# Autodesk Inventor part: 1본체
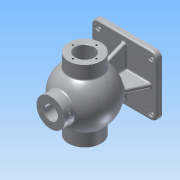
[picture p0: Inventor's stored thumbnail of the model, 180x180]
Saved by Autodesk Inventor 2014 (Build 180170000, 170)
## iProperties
Created: 2017-01
Part Number: 1본체
Material: Aluminum 6061
Document SubType Name: Modeling
Designer: ksu
Density: 2.71 g/cm^3
Appearance: Aluminum - Flat
Mass: 1507.18 g
Surface Area: 1153.3 cm^2
Volume: 556.155 cm^3
Author: ksu
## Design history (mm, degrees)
sketch "Sketch1"
  geometry: L1 (-50.5, -57.5)-(50.5, -57.5); L2 (62.5, -45.5)-(62.5, 45.5); L3 (50.5, 57.5)-(-50.5, 57.5); L4 (-62.5, 45.5)-(-62.5, -45.5); L5 (-62.5, -57.5)-(62.5, 57.5); L6 (62.5, -57.5)-(-62.5, 57.5); A1 r 12 centre (-50.5, 45.5) between (-50.5, 57.5) and (-62.5, 45.5); A2 r 12 centre (-50.5, -45.5) between (-62.5, -45.5) and (-50.5, -57.5); A3 r 12 centre (50.5, -45.5) between (50.5, -57.5) and (62.5, -45.5); A4 r 12 centre (50.5, 45.5) between (62.5, 45.5) and (50.5, 57.5); 1 further point
  constraints: 12 end point, 8 point on circle, 8 point on line, 8 tangent, 4 centre point, 3 equal radius, 2 midpoint, 2 parallel, 1 horizontal, 1 perpendicular
  dimensions: "d0" = 125 distance of L6.end L5.end; "d1" = 115 distance of L5.end L6.start; "d2" = 12 radius of A1
extrude "Extrusion1" new body sketch "Sketch1" distance "d3" = 10; taper "d4" = 0 deg
sketch "Sketch2"
  geometry: L1 (0, 85)-(-53, 85); L2 (-53, 85)-(53, 85); A1 r 53 centre (0, 85) between (53, 85) and (-53, 85); 1 further point
  constraints: 4 end point, 2 point on circle, 1 centre point, 1 collinear, 1 horizontal
  dimensions: "d5" = 106 diameter of A1; "d6" = 85 distance of point (0, 0) L1.start
revolve "Revolution1" sketch "Sketch2" stored, may be unused: angle "d7" = 90 deg
sketch "Sketch3"
  geometry: C1 r 53 at (0, 85) reference; C2 r 31 at (0, 85); 1 further point
  constraints: 1 centre point, 1 coincident
  dimensions: "d8" = 62 diameter of C2
extrude "Extrusion2" join sketch "Sketch3" stored distance "d9" = 136; taper "d10" = 0 deg
workplane "Work Plane1"
sketch "Sketch4"
  geometry: C1 r 27 at (0, 0); 1 further point
  constraints: 1 centre point, 1 coincident
  dimensions: "d12" = 54 diameter of C1
extrude "Extrusion3" join sketch "Sketch4" distance "d13" = 30; taper "d14" = 0 deg
sketch "Sketch5"
  geometry: C1 r 31 at (0, 0) reference; C2 r 17.5 at (0, 0); 1 further point
  constraints: 1 centre point, 1 coincident
  dimensions: "d15" = 35 diameter of C2
extrude "Extrusion4" cut sketch "Sketch5" distance "d16" = 136; taper "d17" = 0 deg
sketch "Sketch6"
  geometry: C1 r 27 at (0, 0) reference; C2 r 13 at (0, 0)
  constraints: 1 centre point, 1 coincident
  dimensions: "d18" = 26 diameter of C2
sketch "Sketch7"
  geometry: L1 (-43, 85)-(43, 85); A1 r 53 centre (0, 85) between (42.988, 116) and (42.988, 54) reference; A2 r 43 centre (0, 85) between (43, 85) and (-43, 85); 1 further point
  constraints: 2 end point, 2 point on circle, 1 centre point, 1 coincident, 1 horizontal
  dimensions: "d19" = 86 diameter of A2
revolve "Revolution2" sketch "Sketch7" stored, may be unused: angle "d20" = 90 deg
sketch "Sketch8"
  geometry: 1 further point
extrude "Extrusion5" cut sketch "Sketch6" distance "d21" = 30; taper "d22" = 0 deg
sketch "Sketch9"
  geometry: 1 further point
sketch "Sketch10"
  geometry: L1 (45.5, 10)-(-45.5, 10) reference; L2 (57.5, 10)-(47.5, 10); L3 (47.5, 10)-(32.011, 48.336); L4 (0, 0)-(0, 23.921); L5 (57.5, 0)-(57.5, 10) reference; L6 (-47.5, 10)-(-32.011, 48.336); L7 (-57.5, 10)-(-45.5, 10); L8 (-47.5, 10)-(47.5, 10); A1 r 53 centre (0, 85) between (42.988, 116) and (42.988, 54) reference; A2 r 48.672 centre (0, 85) between (32.011, 48.336) and (-32.011, 48.336); 2 further points
  constraints: 12 end point, 3 point on circle, 3 point on line, 2 symmetric about line, 1 centre point, 1 coincident, 1 collinear, 1 perpendicular
  dimensions: "d23" = 10 distance of L2.start L2.end; "d24" = 22 deg angle of L5 L3
extrude "Extrusion6" join sketch "Sketch10" stored distance "d25" = 8; taper "d26" = 0 deg
sketch "Sketch12"
  geometry: L1 (50.5, 10)-(-50.5, 10) reference; L2 (62.5, 0)-(62.5, 10) reference; L3 (62.5, 10)-(52.5, 10); L4 (52.5, 10)-(35.258, 52.676); L5 (-62.5, 10)-(-52.5, 10); L6 (-52.5, 10)-(-33.514, 50.872); L7 (-52.5, 10)-(52.5, 10); L8 (-52.5, 10)-(52.5, 10); A1 r 53 centre (0, 85) between (-27, 130.607) and (27, 130.607) reference; A2 r 47.833 centre (0, 85) between (-33.514, 50.872) and (35.258, 52.676); 1 further point
  constraints: 12 end point, 2 collinear, 2 point on circle, 1 centre point, 1 coincident, 1 perpendicular
  dimensions: "d27" = 10 distance of L2.end L3.end; "d83" = 22 deg angle of L2 L4
extrude "Extrusion7" join sketch "Sketch12" stored distance "d28" = 8; taper "d29" = 0 deg
sketch "Sketch13"
  geometry: C1 r 31 at (0, 0) reference; A1 r 24 centre (0, 0) between (0, 24) and (24, 0); 3 further points
  constraints: 4 point on circle, 1 centre point, 1 coincident
  dimensions: "d30" = 48 diameter of A1
hole "Hole1" sketch "Sketch13" at (24, 0), (0, 24), (-24, 0), (0, -24) diameter "d31" = 3.459; stored, may be unused: countersink angle "d35" = 90 deg, drill point angle "d37" = 118 deg; dims "d32" = 16, "d33" = 4, "d34" = 2, "d36" = 19
sketch "Sketch14"
  geometry: C1 r 31 at (0, 0) reference; A1 r 22.5 centre (0, 0) between (0, 22.5) and (22.5, 0); 3 further points
  constraints: 4 point on circle, 1 centre point, 1 coincident
  dimensions: "d38" = 45 diameter of A1
hole "Hole2" sketch "Sketch14" at (-22.5, 0), (0, -22.5), (22.5, 0), (0, 22.5) diameter "d39" = 3.459; stored, may be unused: countersink angle "d43" = 90 deg, drill point angle "d45" = 118 deg; dims "d40" = 12, "d41" = 4, "d42" = 2, "d44" = 15
sketch "Sketch15"
  geometry: L1 (-68, 102.5)-(-39.278, 102.5) reference; L2 (-68, 67.5)-(-39.278, 67.5) reference; L3 (-68, 102.5)-(-52, 102.5); L4 (-52, 102.5)-(-52, 103.5); L5 (-52, 103.5)-(-50.25, 103.5); L6 (-50.25, 103.5)-(-50.25, 85); L7 (0, 85)-(-100.25, 85); L8 (-52, 102.5)-(-52, 85); L9 (-50.25, 85)-(-50.25, 103.5); L10 (-68, 67.5)-(-68, 102.5) reference; 1 further point
  constraints: 14 end point, 4 perpendicular, 3 point on line, 1 collinear, 1 parallel
  dimensions: "d46" = 16 distance of L1.start L3.end; "d47" = 37 diameter of L5 L7; "d48" = 1.75 distance between parallel lines of L8 L6; "d49" = 16 distance between parallel lines of L10 L8 (derived)
revolve "Revolution3" sketch "Sketch15" stored, may be unused: angle "d50" = 90 deg
sketch "Sketch16"
  geometry: 1 further point
sketch "Sketch17"
  geometry: C1 r 27 at (0, 0) reference; A1 r 20 centre (0, 0) between (0, 20) and (20, 0); 2 further points
  constraints: 4 point on circle, 1 centre point, 1 coincident
  dimensions: "d51" = 40 diameter of A1
hole "Hole3" sketch "Sketch17" at (0, -20), (20, 0), (0, 20), (-20, 0) diameter "d52" = 3.459; stored, may be unused: countersink angle "d56" = 90 deg, drill point angle "d58" = 118 deg; dims "d53" = 9, "d54" = 4, "d55" = 2, "d57" = 11
sketch "Sketch18"
  geometry: A1 r 12 centre (-50.5, -45.5) between (-62.5, -45.5) and (-50.5, -57.5) reference; A2 r 12 centre (50.5, -45.5) between (50.5, -57.5) and (62.5, -45.5) reference; A3 r 12 centre (50.5, 45.5) between (62.5, 45.5) and (50.5, 57.5) reference; A4 r 12 centre (-50.5, 45.5) between (-50.5, 57.5) and (-62.5, 45.5) reference; 5 further points
  constraints: 4 coincident
  dimensions: "d59" = 101 distance of point (50.5, 45.5) point (-50.5, 45.5) (derived); "d60" = 91 distance of point (50.5, -45.5) point (50.5, 45.5) (derived)
hole "Hole4" sketch "Sketch18" at (-50.5, -45.5), (-50.5, 45.5), (50.5, -45.5), (50.5, 45.5) diameter "d61" = 8; stored, may be unused: countersink angle "d65" = 90 deg, drill point angle "d67" = 118 deg; dims "d62" = 9, "d63" = 12, "d64" = 3, "d66" = 10
chamfer "Chamfer1" distance "d68" = 1; stored, may be unused: second distance "d69" = 2, angle "d70" = 45 deg
fillet "Fillet1" dims "d71" = 3
fillet "Fillet4" dims "d74" = 3
fillet "Fillet5" dims "d75" = 3
fillet "Fillet6" dims "d76" = 3
fillet "Fillet7" dims "d77" = 3
fillet "Fillet8" dims "d78" = 3
sketch "Sketch19"
  geometry: L1 (-139.383, 31.579)-(-139.383, 59.421); L2 (-139.383, 59.421)-(-140.617, 59.421); L3 (-140.617, 59.421)-(-140.617, 31.579); L4 (-140.617, 31.579)-(-139.383, 31.579); L5 (-140, 31.579)-(-140, 59.421); L6 (-139.383, 45.5)-(-140.617, 45.5); L7 (-150, 18.5)-(-150, 72.5) reference; L8 (-150, 18.5)-(-132.286, 18.5) reference; 1 further point
  constraints: 4 end point, 4 midpoint, 2 other
  dimensions: "d79" = 27 distance between parallel lines of L8 L6; "d80" = 10 distance between parallel lines of L7 L5
emboss "Emboss1" sketch "Sketch19" dims "d0" = 125, "d1" = 115, "d2" = 12, "d7" = 90 deg, "d81" = 0.5, "d82" = 0
body "Solid1"
